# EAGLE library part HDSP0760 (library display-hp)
LED DISPLAY 1-character dot matrix
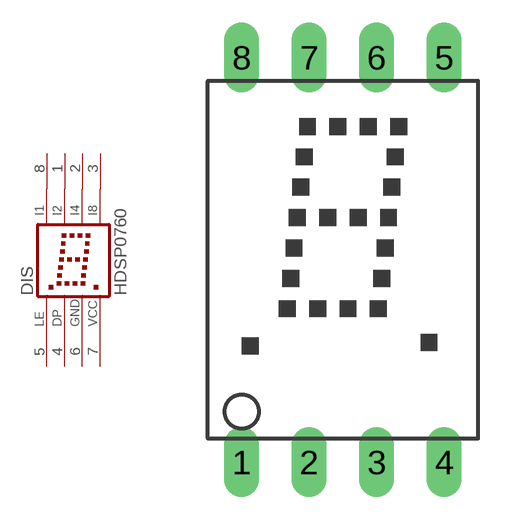
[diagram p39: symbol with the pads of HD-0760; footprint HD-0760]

Designator prefix DIS

## HDSP0760 (MF: AGILENT TECHNOLOGIES; MPN: HDSP-0760; OC_FARNELL: 9869875; OC_NEWARK: 39K9788)  [HD-0760]
1  I2  in
2  I4  in
3  I8  in
4  DP  in
5  LE  in
6  GND  pwr
7  VCC  pwr
8  I1  in

## Footprint HD-0760 (pad centres in mm)
LED DISPLAY 8-mm 1 character dot matrix, 2 decimal points
drill 0.813 long: 1 -3.81,-7.62; 2 -1.27,-7.62; 3 1.27,-7.62; 4 3.81,-7.62; 5 3.81,7.62; 6 1.27,7.62; 7 -1.27,7.62; 8 -3.81,7.62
